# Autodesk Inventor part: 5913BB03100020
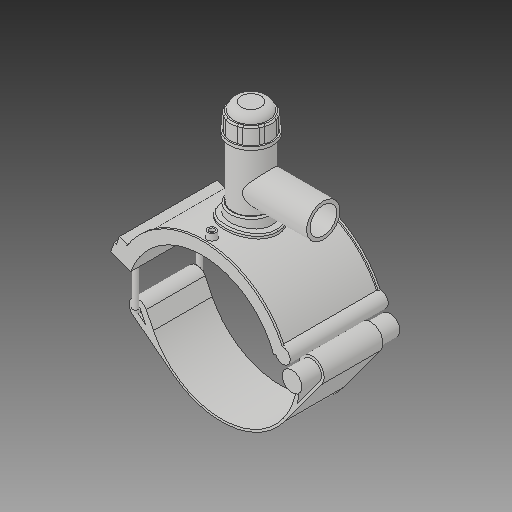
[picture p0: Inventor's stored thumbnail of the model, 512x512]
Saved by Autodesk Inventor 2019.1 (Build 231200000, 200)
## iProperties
Created: 2017-07
Part Number: 5913BB03100020
Material: Generic
Description: PLASSON HIGH VOLUME TAPPING TEE 10''IPS x 2''IPS
Document SubType Name: Modeling
Designer: KIM
Mass: 1712.7 g
Surface Area: 2671.49 cm^2
Volume: 1712.7 cm^3
Density: 1 g/cm^3
Appearance: Default
Author: KIM
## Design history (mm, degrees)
derived "5913B.ipt"
feature "Solid1::5913B.ipt"
feature "Solid2::5913B.ipt"
feature "Solid4::5913B.ipt"
feature "Solid5::5913B.ipt"
tag "TaggingFeature1"
body "Solid1"
body "Solid2"
other parameters: "d0" = 272.7, "d2" = 449.58, "d3" = 68.175, "d4" = 176.022, "d5" = 0, "d6" = 0.1, "d8" = 0, "d40" = 161.65656, "d41" = 95.445, "d43" = 0, "d45" = 0, "d47" = 261.0522, "d78" = 166.35, "d79" = 15, "d80" = 70.4088, "d82" = 5 deg, "d84" = 4, "d85" = 14, "d86" = 0, "d87" = 3, "d88" = 0, "d96" = 317.09556, "d97" = 3.52044, "d98" = 0, "d102" = 2.727, "d120" = 140 deg, "d121" = 24.228, "d122" = 20 deg, "d123" = 777.195, "d124" = 186.5268, "d126" = 0, "d153" = 176.022, "d154" = 0, "d159" = 7.6356, "d162" = 105.6132, "d163" = 0, "d164" = 136.35, "d169" = 4.0905, "d170" = 11.4534, "d172" = 0, "d173" = 1, "d175" = 136.35, "d176" = 20 deg, "d177" = 19.089, "d178" = 38.178, "d180" = 0, "d183" = 15.2712, "d184" = 15.2712, "d187" = 155.439, "d188" = 11.4534, "d189" = 19.089, "d190" = 0, "d191" = 233.1585, "d193" = 9.8172, "d194" = 4.9086, "d195" = 90 deg, "d197" = 0, "d199" = 0, "d200" = 19.089, "d202" = 0, "d203" = 194.818, "d204" = 74.35165, "d205" = 54.78543, "d206" = 66.52516, "d207" = 146.1135, "d208" = 151.95804, "d209" = 181.18074, "d210" = 67.30781, "d211" = 78.2649, "d212" = 62.61192, "d213" = 40.392, "d216" = 0, "d217" = 27.27, "d218" = 13.635, "d219" = 2.727, "d222" = 272.7, "d224" = 0, "d230" = 2.727, "d257" = 211.28, "d258" = 129.794, "d259" = 48.08, "d260" = 60.1, "d263" = 179.832, "d265" = 0, "d267" = 13.00006, "d268" = 2.60001, "d269" = 2.60001, "d271" = 2.60001, "d273" = 0, "d274" = 23.56194, "d275" = 218.16, "d277" = 109.08, "d278" = 436.32, "d280" = 0, "d281" = 272.7, "d283" = 0, "d285" = 0, "d290" = 27.27, "d291" = 35.451, "d293" = 149.985, "d294" = 140.4405, "d296" = 40.905, "d297" = 32.724, "d_" = 272.7, "B_" = 179.832, "L_" = 176.022, "d_t" = 6, "H_2" = 194.818, "H_1" = 74.93, "d_1" = 60.1, "H_" = 129.794, "d1" = 310.878, "d192" = 9.8172
